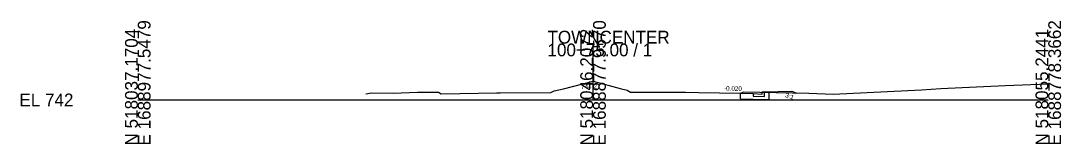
# Model space of a CAD drawing. Extents: x -26 to 203, y -10 to 4027.
# Drawn here: x -25.7 to 202.8, y 1490.3 to 1517.3 of the extents above; entities that cross this region are included whole.
import ezdxf

# ---------------------------------------------------------------- set-up
doc = ezdxf.new("R2010")
doc.units = 0
for name, color, linetype in [('Default', 7, 'Continuous'), ('DESIGN - SHEET - Light Grid', 7, 'Continuous'), ('DESIGN - TYPICAL - Finished Grade and Subgrade', 7, 'Continuous'), ('DESIGN - TYPICAL - Finished Grade Slopes Text', 7, 'Continuous'), ('SURVEY - GROUND - Top of Ground', 7, 'Continuous')]:
    doc.layers.add(name, color=color, linetype=linetype)

msp = doc.modelspace()

# ---------------------------------------------------------------- linework, layer by layer
at = {"layer": 'DESIGN - SHEET - Light Grid'}
for p, q in [((100, 1500), (100, 1512.36)), ((0, 1500), (100, 1500)), ((100, 1500), (200, 1500))]:
    msp.add_line(p, q, dxfattribs=at)
at = {"layer": 'DESIGN - TYPICAL - Finished Grade and Subgrade'}
for p, q in [((132.38, 1500.25), (132.38, 1501.5)), ((132.38, 1501.5), (135.16, 1501.44)), ((137.16, 1501.27), (137.17, 1501.75)), ((137.17, 1501.75), (137.66, 1501.77)), ((137.66, 1501.77), (143.66, 1501.89)), ((137.66, 1500.77), (137.66, 1501.77)), ((138.66, 1500.12), (138.66, 1501.79)), ((143.66, 1501.89), (144.79, 1501.51)), ((132.38, 1500.25), (135.16, 1500.19)), ((135.16, 1501.44), (137.16, 1501.27)), ((135.16, 1501.44), (135.16, 1500.82)), ((135.16, 1500.82), (137.66, 1500.77)), ((135.16, 1500.19), (138.66, 1500.12))]:
    msp.add_line(p, q, dxfattribs=at)
at = {"layer": 'SURVEY - GROUND - Top of Ground'}
msp.add_lwpolyline([(50.09, 1501.31), (51.32, 1501.56), (56.08, 1501.47), (61.45, 1501.68), (66.08, 1501.69), (66.62, 1501.34), (78.87, 1501.53), (79.63, 1501.54), (90.73, 1501.66), (91.49, 1501.99), (93.51, 1502.42), (100.02, 1504.12), (105.97, 1502.52), (107.52, 1502.14), (108.21, 1501.73), (117.17, 1501.68), (120.29, 1501.67), (123.15, 1501.64), (132.38, 1501.5), (133.07, 1501.79), (147.38, 1501.45), (152.75, 1501.3), (172.16, 1502.2), (176.41, 1502.51), (190.54, 1503.17), (200, 1503.56)], dxfattribs=at)

# ---------------------------------------------------------------- texts
at = {"layer": 'Default'}
msp.add_text('744.27', height=1, dxfattribs=at).set_placement((97.39, 1502.43))
at = {"layer": 'DESIGN - SHEET - Light Grid'}
for s, p in [('N 518037.1704', (0, 1490)), ('E 1688977.5479', (2.8, 1490)), ('N 518046.2072', (100, 1490)), ('E 1688877.9570', (102.8, 1490)), ('N 518055.2441', (200, 1490)), ('E 1688778.3662', (202.8, 1490))]:
    msp.add_text(s, height=2.8, rotation=90, dxfattribs=at).set_placement(p)
for s, p in [('TOWNCENTER', (90, 1512.36)), ('100+75.00 / 1', (90, 1509.56)), ('EL 742', (-26, 1498.6))]:
    msp.add_text(s, height=2.8, dxfattribs=at).set_placement(p)
at = {"layer": 'DESIGN - TYPICAL - Finished Grade Slopes Text'}
for s, rotation, p in [('-0.020', 358.8542, (128.77, 1502.04)), ('3:1', 341.5651, (142.13, 1500.65))]:
    msp.add_text(s, height=1, rotation=rotation, dxfattribs=at).set_placement(p)

doc.saveas('drawing.dxf')
